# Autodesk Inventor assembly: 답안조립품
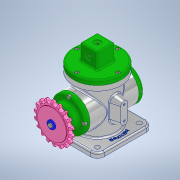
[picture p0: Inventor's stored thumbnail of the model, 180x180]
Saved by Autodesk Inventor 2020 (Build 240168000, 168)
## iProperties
Created: 2021-03
Part Number: 답안조립품
Document SubType Name: Assembly
Designer: USER
Author: USER
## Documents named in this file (19)
- C:\Users\USER\Desktop\710306V1010\답안조립품.iam
- C:\Users\USER\Desktop\710306V1010\본체.ipt
- C:\Users\USER\Desktop\710306V1010\E-링.ipt
- C:\Users\USER\Desktop\710306V1010\덮개.ipt
- C:\Users\USER\Desktop\710306V1010\뒤커버.ipt
- C:\Users\USER\Desktop\710306V1010\링크.ipt
- C:\Users\USER\Desktop\710306V1010\멈춤나사 M3.ipt
- C:\Users\USER\Desktop\710306V1010\베어링 17 x 40 x 12.ipt
- C:\Users\USER\Desktop\710306V1010\볼트 M4 x 8.ipt
- C:\Users\USER\Desktop\710306V1010\볼트 M4 x 10.ipt
- C:\Users\USER\Desktop\710306V1010\스프로킷.ipt
- C:\Users\USER\Desktop\710306V1010\슬라이더.ipt
- C:\Users\USER\Desktop\710306V1010\앞커버.ipt
- C:\Users\USER\Desktop\710306V1010\오일 실 17 30 8.ipt
- C:\Users\USER\Desktop\710306V1010\와셔 4x16.ipt
- C:\Users\USER\Desktop\710306V1010\클레비스 핀 6 x 22.ipt
- 클레비스 핀 6 x 22.ipt
- C:\Users\USER\Desktop\710306V1010\키 4 x 4 x 12.ipt
- C:\Users\USER\Desktop\710306V1010\편심축.ipt
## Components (1 placed, 1 different names)
1. E-링:1
